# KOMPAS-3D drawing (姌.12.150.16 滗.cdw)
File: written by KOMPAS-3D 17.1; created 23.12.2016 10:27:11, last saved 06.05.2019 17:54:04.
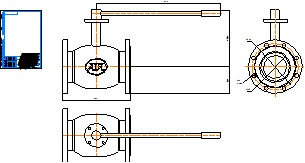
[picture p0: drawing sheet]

Sheet 1: A4, portrait

Title block, sheet 1: name: КШ.12.150.16 фф; material: Внимание! Данный продукт является объектом авторского права ООО «Торговый Дом АДЛ». / Запрещается изменение, копирование, распространение / (в том числе путем копирования на другие сайты и ресурсы в Интернете) / или любое иное использование информации и объектов без предварительного / согласия правообладателя (ООО «Торговый Дом АДЛ»).; sheets: 1; organisation: ООО "Торговый дом АДЛ"; sheet format: A4; stored path: C:\Users\tra\Desktop\2д чертежи\Шаровые краны БИВАЛ\КШ_Бивал_серия_11_12\KOMPAS_2D\КШ.12.150.16 фф.cdw

Views: Вид 1, Проекционный вид 2, Проекционный вид 3
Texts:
  Klimkovich
  ADL
Dimensions and other numbers on the sheet: 350; 645; 291,6; 140; 240; 149; 22; 8 Отв.; 1:1; 1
